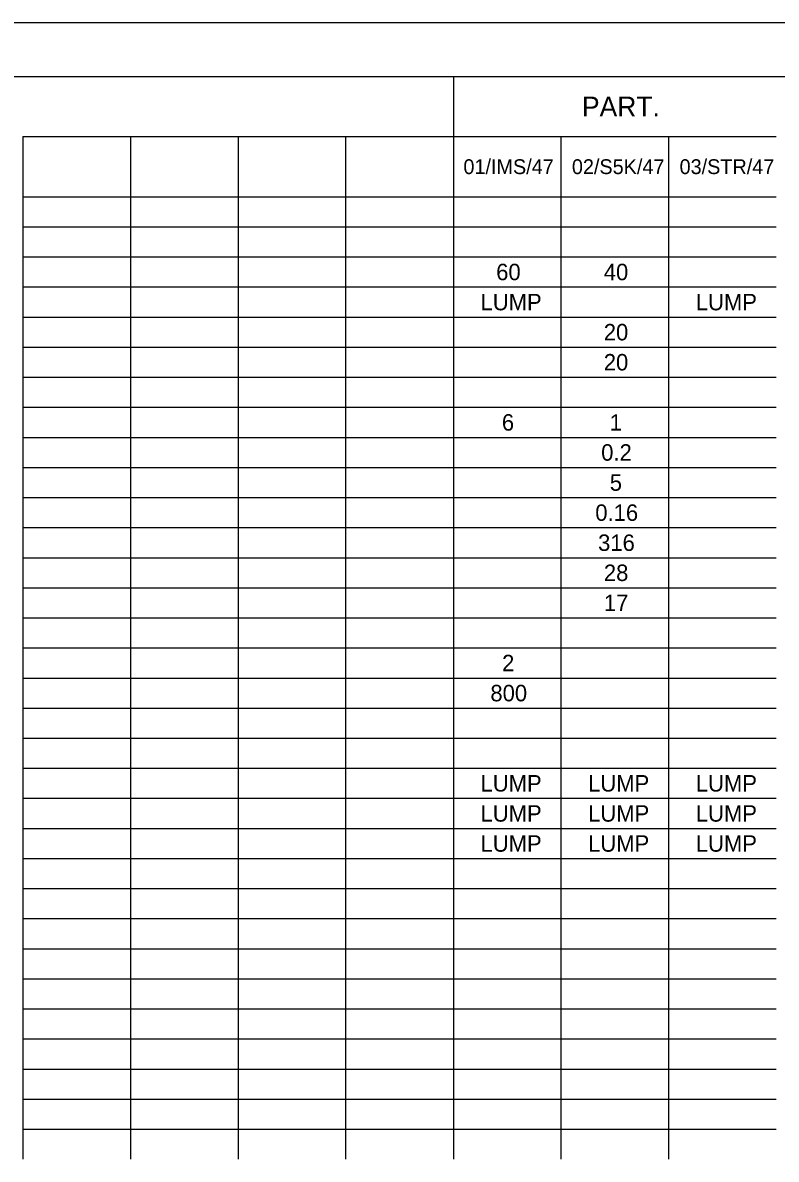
# Model space of a CAD drawing. Extents: x 0 to 34, y 0 to 22.
# Drawn here: x 8.52 to 15.54, y 11.42 to 22 of the extents above; entities that cross this region are included whole.
import ezdxf

# ---------------------------------------------------------------- set-up
doc = ezdxf.new("R2010")
doc.units = 0
for name, color, linetype in [('SH_Border', 7, 'Continuous'), ('SH_Cut_Line', 7, 'Continuous'), ('SH_Text', 7, 'Continuous')]:
    doc.layers.add(name, color=color, linetype=linetype)

msp = doc.modelspace()

# ---------------------------------------------------------------- linework, layer by layer
at = {"layer": 'SH_Border'}
msp.add_lwpolyline([(1.5, 21.5), (33.5, 21.5), (33.5, 0.5), (1.5, 0.5)], close=True, dxfattribs=at)
at = {"layer": 'SH_Cut_Line'}
msp.add_lwpolyline([(0, 0), (34, 0), (34, 22), (0, 22)], close=True, dxfattribs=at)
at = {"layer": 'SH_Text'}
for p, q in [((8.518, 21.5), (9.52, 21.5)), ((9.52, 21.5), (11.525, 21.5)), ((11.525, 21.5), (12.528, 21.5)), ((12.528, 21.5), (13.53, 21.5)), ((12.528, 21.5), (12.528, 21.22)), ((13.53, 21.5), (14.533, 21.5)), ((14.533, 21.5), (15.535, 21.5)), ((12.528, 21.22), (12.528, 20.94)), ((8.518, 20.94), (9.52, 20.94)), ((8.518, 20.94), (8.518, 20.66)), ((9.52, 20.94), (11.525, 20.94)), ((9.52, 20.94), (9.52, 20.66)), ((10.523, 20.94), (10.523, 20.66)), ((11.525, 20.94), (12.528, 20.94)), ((11.525, 20.94), (11.525, 20.66)), ((12.528, 20.94), (13.53, 20.94)), ((12.528, 20.94), (12.528, 20.66)), ((13.53, 20.94), (14.533, 20.94)), ((13.53, 20.94), (13.53, 20.66)), ((14.533, 20.94), (15.535, 20.94)), ((14.533, 20.94), (14.533, 20.66)), ((8.518, 20.66), (8.518, 20.38)), ((9.52, 20.66), (9.52, 20.38)), ((10.523, 20.66), (10.523, 20.38)), ((11.525, 20.66), (11.525, 20.38)), ((12.528, 20.66), (12.528, 20.38)), ((13.53, 20.66), (13.53, 20.38)), ((14.533, 20.66), (14.533, 20.38)), ((8.518, 20.38), (9.52, 20.38)), ((8.518, 20.38), (8.518, 20.1)), ((9.52, 20.38), (11.525, 20.38)), ((9.52, 20.38), (9.52, 20.1)), ((10.523, 20.38), (10.523, 20.1)), ((11.525, 20.38), (12.528, 20.38)), ((11.525, 20.38), (11.525, 20.1)), ((12.528, 20.38), (13.53, 20.38)), ((12.528, 20.38), (12.528, 20.1)), ((13.53, 20.38), (14.533, 20.38)), ((13.53, 20.38), (13.53, 20.1)), ((14.533, 20.38), (15.535, 20.38)), ((14.533, 20.38), (14.533, 20.1)), ((8.518, 20.1), (9.52, 20.1)), ((8.518, 20.1), (8.518, 18.7)), ((9.52, 20.1), (11.525, 20.1)), ((9.52, 20.1), (9.52, 18.7)), ((10.523, 20.1), (10.523, 18.7)), ((11.525, 20.1), (12.528, 20.1)), ((11.525, 20.1), (11.525, 18.7)), ((12.528, 20.1), (13.53, 20.1)), ((12.528, 20.1), (12.528, 18.7)), ((13.53, 20.1), (14.533, 20.1)), ((13.53, 20.1), (13.53, 18.7)), ((14.533, 20.1), (15.535, 20.1)), ((14.533, 20.1), (14.533, 18.7)), ((8.518, 19.82), (9.52, 19.82)), ((9.52, 19.82), (11.525, 19.82)), ((11.525, 19.82), (12.528, 19.82)), ((12.528, 19.82), (13.53, 19.82)), ((13.53, 19.82), (14.533, 19.82)), ((14.533, 19.82), (15.535, 19.82)), ((8.518, 19.54), (9.52, 19.54)), ((9.52, 19.54), (11.525, 19.54)), ((11.525, 19.54), (12.528, 19.54)), ((12.528, 19.54), (13.53, 19.54)), ((13.53, 19.54), (14.533, 19.54)), ((14.533, 19.54), (15.535, 19.54)), ((8.518, 19.26), (9.52, 19.26)), ((9.52, 19.26), (11.525, 19.26)), ((11.525, 19.26), (12.528, 19.26)), ((12.528, 19.26), (13.53, 19.26)), ((13.53, 19.26), (14.533, 19.26)), ((14.533, 19.26), (15.535, 19.26)), ((8.518, 18.98), (9.52, 18.98)), ((9.52, 18.98), (11.525, 18.98)), ((11.525, 18.98), (12.528, 18.98)), ((12.528, 18.98), (13.53, 18.98)), ((13.53, 18.98), (14.533, 18.98)), ((14.533, 18.98), (15.535, 18.98)), ((8.518, 18.7), (9.52, 18.7)), ((8.518, 18.7), (8.518, 18.14)), ((9.52, 18.7), (11.525, 18.7)), ((9.52, 18.7), (9.52, 18.14)), ((10.523, 18.7), (10.523, 18.14)), ((11.525, 18.7), (12.528, 18.7)), ((11.525, 18.7), (11.525, 18.14)), ((12.528, 18.7), (13.53, 18.7)), ((12.528, 18.7), (12.528, 18.14)), ((13.53, 18.7), (14.533, 18.7)), ((13.53, 18.7), (13.53, 18.14)), ((14.533, 18.7), (15.535, 18.7)), ((14.533, 18.7), (14.533, 18.14)), ((8.518, 18.42), (9.52, 18.42)), ((9.52, 18.42), (11.525, 18.42)), ((11.525, 18.42), (12.528, 18.42)), ((12.528, 18.42), (13.53, 18.42)), ((13.53, 18.42), (14.533, 18.42)), ((14.533, 18.42), (15.535, 18.42)), ((8.518, 18.14), (9.52, 18.14)), ((8.518, 18.14), (8.518, 17.86)), ((9.52, 18.14), (11.525, 18.14)), ((9.52, 18.14), (9.52, 17.86)), ((10.523, 18.14), (10.523, 17.86)), ((11.525, 18.14), (12.528, 18.14)), ((11.525, 18.14), (11.525, 17.86)), ((12.528, 18.14), (13.53, 18.14)), ((12.528, 18.14), (12.528, 17.86)), ((13.53, 18.14), (14.533, 18.14)), ((13.53, 18.14), (13.53, 17.86)), ((14.533, 18.14), (15.535, 18.14)), ((14.533, 18.14), (14.533, 17.86)), ((8.518, 17.86), (9.52, 17.86)), ((8.518, 17.86), (8.518, 17.58)), ((9.52, 17.86), (11.525, 17.86)), ((9.52, 17.86), (9.52, 17.58)), ((10.523, 17.86), (10.523, 17.58)), ((11.525, 17.86), (12.528, 17.86)), ((11.525, 17.86), (11.525, 17.58)), ((12.528, 17.86), (13.53, 17.86)), ((12.528, 17.86), (12.528, 17.58)), ((13.53, 17.86), (14.533, 17.86)), ((13.53, 17.86), (13.53, 17.58)), ((14.533, 17.86), (15.535, 17.86)), ((14.533, 17.86), (14.533, 17.58)), ((8.518, 17.58), (9.52, 17.58)), ((8.518, 17.58), (8.518, 17.3)), ((9.52, 17.58), (11.525, 17.58)), ((9.52, 17.58), (9.52, 17.3)), ((10.523, 17.58), (10.523, 17.3)), ((11.525, 17.58), (12.528, 17.58)), ((11.525, 17.58), (11.525, 17.3)), ((12.528, 17.58), (13.53, 17.58)), ((12.528, 17.58), (12.528, 17.3)), ((13.53, 17.58), (14.533, 17.58)), ((13.53, 17.58), (13.53, 17.3)), ((14.533, 17.58), (15.535, 17.58)), ((14.533, 17.58), (14.533, 17.3)), ((8.518, 17.3), (9.52, 17.3)), ((8.518, 17.3), (8.518, 17.02)), ((9.52, 17.3), (11.525, 17.3)), ((9.52, 17.3), (9.52, 17.02)), ((10.523, 17.3), (10.523, 17.02)), ((11.525, 17.3), (12.528, 17.3)), ((11.525, 17.3), (11.525, 17.02)), ((12.528, 17.3), (13.53, 17.3)), ((12.528, 17.3), (12.528, 17.02)), ((13.53, 17.3), (14.533, 17.3)), ((13.53, 17.3), (13.53, 17.02)), ((14.533, 17.3), (15.535, 17.3)), ((14.533, 17.3), (14.533, 17.02)), ((8.518, 17.02), (9.52, 17.02)), ((8.518, 17.02), (8.518, 16.74)), ((9.52, 17.02), (11.525, 17.02)), ((9.52, 17.02), (9.52, 16.74)), ((10.523, 17.02), (10.523, 16.74)), ((11.525, 17.02), (12.528, 17.02)), ((11.525, 17.02), (11.525, 16.74)), ((12.528, 17.02), (13.53, 17.02)), ((12.528, 17.02), (12.528, 16.74)), ((13.53, 17.02), (14.533, 17.02)), ((13.53, 17.02), (13.53, 16.74)), ((14.533, 17.02), (15.535, 17.02)), ((14.533, 17.02), (14.533, 16.74)), ((8.518, 16.74), (9.52, 16.74)), ((8.518, 16.74), (8.518, 16.18)), ((9.52, 16.74), (11.525, 16.74)), ((9.52, 16.74), (9.52, 16.18)), ((10.523, 16.74), (10.523, 16.18)), ((11.525, 16.74), (12.528, 16.74)), ((11.525, 16.74), (11.525, 16.18)), ((12.528, 16.74), (13.53, 16.74)), ((12.528, 16.74), (12.528, 16.18)), ((13.53, 16.74), (14.533, 16.74)), ((13.53, 16.74), (13.53, 16.18)), ((14.533, 16.74), (15.535, 16.74)), ((14.533, 16.74), (14.533, 16.18)), ((8.518, 16.46), (9.52, 16.46)), ((9.52, 16.46), (11.525, 16.46)), ((11.525, 16.46), (12.528, 16.46)), ((12.528, 16.46), (13.53, 16.46)), ((13.53, 16.46), (14.533, 16.46)), ((14.533, 16.46), (15.535, 16.46)), ((8.518, 16.18), (9.52, 16.18)), ((8.518, 16.18), (8.518, 15.9)), ((9.52, 16.18), (11.525, 16.18)), ((9.52, 16.18), (9.52, 15.9)), ((10.523, 16.18), (10.523, 15.9)), ((11.525, 16.18), (12.528, 16.18)), ((11.525, 16.18), (11.525, 15.9)), ((12.528, 16.18), (13.53, 16.18)), ((12.528, 16.18), (12.528, 15.9)), ((13.53, 16.18), (14.533, 16.18)), ((13.53, 16.18), (13.53, 15.9)), ((14.533, 16.18), (15.535, 16.18)), ((14.533, 16.18), (14.533, 15.9)), ((8.518, 15.9), (9.52, 15.9)), ((8.518, 15.9), (8.518, 15.62)), ((9.52, 15.9), (11.525, 15.9)), ((9.52, 15.9), (9.52, 15.62)), ((10.523, 15.9), (10.523, 15.62)), ((11.525, 15.9), (12.528, 15.9)), ((11.525, 15.9), (11.525, 15.62)), ((12.528, 15.9), (13.53, 15.9)), ((12.528, 15.9), (12.528, 15.62)), ((13.53, 15.9), (14.533, 15.9)), ((13.53, 15.9), (13.53, 15.62)), ((14.533, 15.9), (15.535, 15.9)), ((14.533, 15.9), (14.533, 15.62)), ((8.518, 15.62), (9.52, 15.62)), ((8.518, 15.62), (8.518, 15.34)), ((9.52, 15.62), (11.525, 15.62)), ((9.52, 15.62), (9.52, 15.34)), ((10.523, 15.62), (10.523, 15.34)), ((11.525, 15.62), (12.528, 15.62)), ((11.525, 15.62), (11.525, 15.34)), ((12.528, 15.62), (13.53, 15.62)), ((12.528, 15.62), (12.528, 15.34)), ((13.53, 15.62), (14.533, 15.62)), ((13.53, 15.62), (13.53, 15.34)), ((14.533, 15.62), (15.535, 15.62)), ((14.533, 15.62), (14.533, 15.34)), ((8.518, 15.34), (9.52, 15.34)), ((8.518, 15.34), (8.518, 14.78)), ((9.52, 15.34), (11.525, 15.34)), ((9.52, 15.34), (9.52, 14.78)), ((10.523, 15.34), (10.523, 14.78)), ((11.525, 15.34), (12.528, 15.34)), ((11.525, 15.34), (11.525, 14.78)), ((12.528, 15.34), (13.53, 15.34)), ((12.528, 15.34), (12.528, 14.78)), ((13.53, 15.34), (14.533, 15.34)), ((13.53, 15.34), (13.53, 14.78)), ((14.533, 15.34), (15.535, 15.34)), ((14.533, 15.34), (14.533, 14.78)), ((8.518, 15.06), (9.52, 15.06)), ((9.52, 15.06), (11.525, 15.06)), ((11.525, 15.06), (12.528, 15.06)), ((12.528, 15.06), (13.53, 15.06)), ((13.53, 15.06), (14.533, 15.06)), ((14.533, 15.06), (15.535, 15.06)), ((8.518, 14.78), (9.52, 14.78)), ((8.518, 14.78), (8.518, 14.5)), ((9.52, 14.78), (11.525, 14.78)), ((9.52, 14.78), (9.52, 14.5)), ((10.523, 14.78), (10.523, 14.5)), ((11.525, 14.78), (12.528, 14.78)), ((11.525, 14.78), (11.525, 14.5)), ((12.528, 14.78), (13.53, 14.78)), ((12.528, 14.78), (12.528, 14.5)), ((13.53, 14.78), (14.533, 14.78)), ((13.53, 14.78), (13.53, 14.5)), ((14.533, 14.78), (15.535, 14.78)), ((14.533, 14.78), (14.533, 14.5)), ((8.518, 14.5), (9.52, 14.5)), ((8.518, 14.5), (8.518, 14.22)), ((9.52, 14.5), (11.525, 14.5)), ((9.52, 14.5), (9.52, 14.22)), ((10.523, 14.5), (10.523, 14.22)), ((11.525, 14.5), (12.528, 14.5)), ((11.525, 14.5), (11.525, 14.22)), ((12.528, 14.5), (13.53, 14.5)), ((12.528, 14.5), (12.528, 14.22)), ((13.53, 14.5), (14.533, 14.5)), ((13.53, 14.5), (13.53, 14.22)), ((14.533, 14.5), (15.535, 14.5)), ((14.533, 14.5), (14.533, 14.22)), ((8.518, 14.22), (9.52, 14.22)), ((8.518, 14.22), (8.518, 13.94)), ((9.52, 14.22), (11.525, 14.22)), ((9.52, 14.22), (9.52, 13.94)), ((10.523, 14.22), (10.523, 13.94)), ((11.525, 14.22), (12.528, 14.22)), ((11.525, 14.22), (11.525, 13.94)), ((12.528, 14.22), (13.53, 14.22)), ((12.528, 14.22), (12.528, 13.94)), ((13.53, 14.22), (14.533, 14.22)), ((13.53, 14.22), (13.53, 13.94)), ((14.533, 14.22), (15.535, 14.22)), ((14.533, 14.22), (14.533, 13.94)), ((8.518, 13.94), (9.52, 13.94)), ((8.518, 13.94), (8.518, 11.7)), ((9.52, 13.94), (11.525, 13.94)), ((9.52, 13.94), (9.52, 11.7)), ((10.523, 13.94), (10.523, 11.7)), ((11.525, 13.94), (12.528, 13.94)), ((11.525, 13.94), (11.525, 11.7)), ((12.528, 13.94), (13.53, 13.94)), ((12.528, 13.94), (12.528, 11.7)), ((13.53, 13.94), (14.533, 13.94)), ((13.53, 13.94), (13.53, 11.7)), ((14.533, 13.94), (15.535, 13.94)), ((14.533, 13.94), (14.533, 11.7)), ((8.518, 13.66), (9.52, 13.66)), ((9.52, 13.66), (11.525, 13.66)), ((11.525, 13.66), (12.528, 13.66)), ((12.528, 13.66), (13.53, 13.66)), ((13.53, 13.66), (14.533, 13.66)), ((14.533, 13.66), (15.535, 13.66)), ((8.518, 13.38), (9.52, 13.38)), ((9.52, 13.38), (11.525, 13.38)), ((11.525, 13.38), (12.528, 13.38)), ((12.528, 13.38), (13.53, 13.38)), ((13.53, 13.38), (14.533, 13.38)), ((14.533, 13.38), (15.535, 13.38)), ((8.518, 13.1), (9.52, 13.1)), ((9.52, 13.1), (11.525, 13.1)), ((11.525, 13.1), (12.528, 13.1)), ((12.528, 13.1), (13.53, 13.1)), ((13.53, 13.1), (14.533, 13.1)), ((14.533, 13.1), (15.535, 13.1)), ((8.518, 12.82), (9.52, 12.82)), ((9.52, 12.82), (11.525, 12.82)), ((11.525, 12.82), (12.528, 12.82)), ((12.528, 12.82), (13.53, 12.82)), ((13.53, 12.82), (14.533, 12.82)), ((14.533, 12.82), (15.535, 12.82)), ((8.518, 12.54), (9.52, 12.54)), ((9.52, 12.54), (11.525, 12.54)), ((11.525, 12.54), (12.528, 12.54)), ((12.528, 12.54), (13.53, 12.54)), ((13.53, 12.54), (14.533, 12.54)), ((14.533, 12.54), (15.535, 12.54)), ((8.518, 12.26), (9.52, 12.26)), ((9.52, 12.26), (11.525, 12.26)), ((11.525, 12.26), (12.528, 12.26)), ((12.528, 12.26), (13.53, 12.26)), ((13.53, 12.26), (14.533, 12.26)), ((14.533, 12.26), (15.535, 12.26)), ((8.518, 11.98), (9.52, 11.98)), ((9.52, 11.98), (11.525, 11.98)), ((11.525, 11.98), (12.528, 11.98)), ((12.528, 11.98), (13.53, 11.98)), ((13.53, 11.98), (14.533, 11.98)), ((14.533, 11.98), (15.535, 11.98)), ((8.518, 11.7), (9.52, 11.7)), ((8.518, 11.7), (8.518, 11.42)), ((9.52, 11.7), (11.525, 11.7)), ((9.52, 11.7), (9.52, 11.42)), ((10.523, 11.7), (10.523, 11.42)), ((11.525, 11.7), (12.528, 11.7)), ((11.525, 11.7), (11.525, 11.42)), ((12.528, 11.7), (13.53, 11.7)), ((12.528, 11.7), (12.528, 11.42)), ((13.53, 11.7), (14.533, 11.7)), ((13.53, 11.7), (13.53, 11.42)), ((14.533, 11.7), (15.535, 11.7)), ((14.533, 11.7), (14.533, 11.42))]:
    msp.add_line(p, q, dxfattribs=at)

# ---------------------------------------------------------------- texts
for s, height, p in [('PART.', 0.184, (13.726, 21.128)), ('01/IMS/47', 0.138, (12.622, 20.591)), ('02/S5K/47', 0.138, (13.632, 20.591)), ('03/STR/47', 0.138, (14.635, 20.591)), ('60', 0.1533, (12.927, 19.603)), ('40', 0.1533, (13.929, 19.603)), ('LUMP', 0.1533, (12.781, 19.323)), ('LUMP', 0.1533, (14.786, 19.323)), ('20', 0.1533, (13.929, 19.043)), ('20', 0.1533, (13.929, 18.763)), ('6', 0.153, (12.98, 18.203)), ('1', 0.153, (13.984, 18.203)), ('0.2', 0.1533, (13.905, 17.923)), ('5', 0.153, (13.985, 17.643)), ('0.16', 0.1533, (13.85, 17.363)), ('316', 0.1533, (13.876, 17.083)), ('28', 0.1533, (13.93, 16.803)), ('17', 0.1533, (13.93, 16.523)), ('2', 0.153, (12.982, 15.963)), ('800', 0.1533, (12.873, 15.683)), ('LUMP', 0.1533, (12.781, 14.843)), ('LUMP', 0.1533, (13.783, 14.843)), ('LUMP', 0.1533, (14.786, 14.843)), ('LUMP', 0.1533, (12.781, 14.563)), ('LUMP', 0.1533, (13.783, 14.563)), ('LUMP', 0.1533, (14.786, 14.563)), ('LUMP', 0.1533, (12.781, 14.283)), ('LUMP', 0.1533, (13.783, 14.283)), ('LUMP', 0.1533, (14.786, 14.283))]:
    msp.add_text(s, height=height, dxfattribs=at).set_placement(p)

doc.saveas('drawing.dxf')
